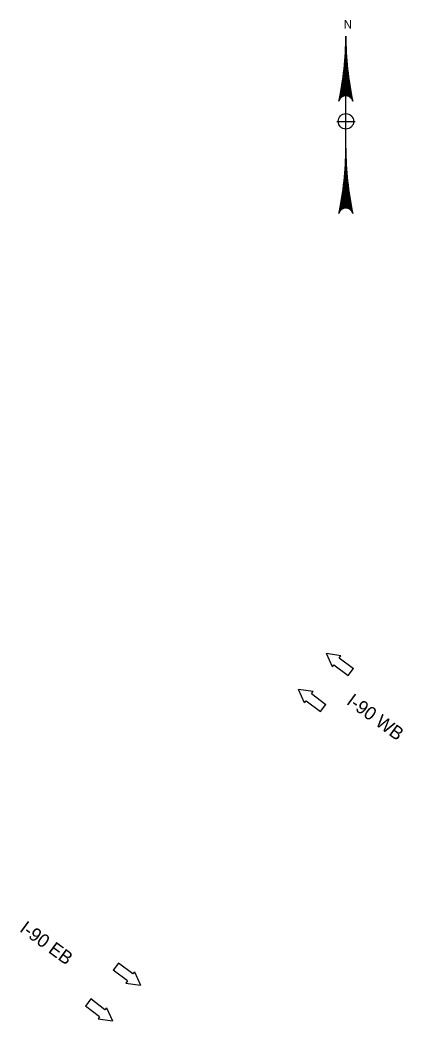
# Model space of a CAD drawing. Extents: x 337137 to 337603, y 1540940 to 1541587.
# Drawn here: x 337136.6 to 337226.9, y 1541351.2 to 1541586.5 of the extents above; entities that cross this region are included whole.
import ezdxf

# ---------------------------------------------------------------- set-up
doc = ezdxf.new("R2010")
doc.units = 0
for name, color, linetype in [('O_Details_Dimensions_Notes_P', 7, 'Continuous'), ('O_Details_Object Line 1_P', 7, 'Continuous'), ('O_Details_Text Normal Proposed_P_T', 7, 'Continuous')]:
    doc.layers.add(name, color=color, linetype=linetype)

msp = doc.modelspace()

# ---------------------------------------------------------------- linework, layer by layer
at = {"layer": 'O_Details_Object Line 1_P'}
for p, q in [((337212.06, 1541437.04), (337208.67, 1541437.53)), ((337210.07, 1541434.41), (337208.67, 1541437.53)), ((337211.69, 1541436.56), (337212.06, 1541437.04)), ((337211.69, 1541436.56), (337215.05, 1541434.04)), ((337210.07, 1541434.41), (337210.43, 1541434.89)), ((337210.43, 1541434.89), (337213.79, 1541432.36)), ((337213.79, 1541432.36), (337215.05, 1541434.04)), ((337205.51, 1541428.61), (337202.13, 1541429.1)), ((337203.53, 1541425.97), (337202.13, 1541429.1)), ((337205.15, 1541428.13), (337205.51, 1541428.61)), ((337205.15, 1541428.13), (337208.51, 1541425.6)), ((337203.53, 1541425.97), (337203.89, 1541426.45)), ((337203.89, 1541426.45), (337207.25, 1541423.93)), ((337207.25, 1541423.93), (337208.51, 1541425.6)), ((337159.79, 1541364.77), (337158.53, 1541363.09)), ((337161.89, 1541360.57), (337158.53, 1541363.09)), ((337163.15, 1541362.24), (337159.79, 1541364.77)), ((337163.51, 1541362.72), (337163.15, 1541362.24)), ((337163.51, 1541362.72), (337164.92, 1541359.6)), ((337161.89, 1541360.57), (337161.53, 1541360.09)), ((337161.53, 1541360.09), (337164.92, 1541359.6)), ((337153.25, 1541356.34), (337151.99, 1541354.66)), ((337156.61, 1541353.81), (337153.25, 1541356.34)), ((337155.35, 1541352.13), (337151.99, 1541354.66)), ((337156.97, 1541354.29), (337156.61, 1541353.81)), ((337156.97, 1541354.29), (337158.37, 1541351.17)), ((337155.35, 1541352.13), (337154.99, 1541351.65)), ((337154.99, 1541351.65), (337158.37, 1541351.17))]:
    msp.add_line(p, q, dxfattribs=at)
at = {"layer": 'O_Details_Text Normal Proposed_P_T'}
for p, q in [((337213.23, 1541542.27), (337213.23, 1541582.73)), ((337213.23, 1541542.27), (337213.23, 1541582.73)), ((337213.23, 1541542.27), (337213.23, 1541582.73)), ((337213.23, 1541542.27), (337213.23, 1541582.73)), ((337213.03, 1541568.63), (337213.03, 1541577.23)), ((337213.12, 1541568.65), (337213.12, 1541578.79)), ((337213.33, 1541568.65), (337213.33, 1541578.79)), ((337213.43, 1541568.63), (337213.43, 1541577.23)), ((337212.86, 1541568.6), (337212.86, 1541575.24)), ((337212.95, 1541568.63), (337212.95, 1541576.05)), ((337213.52, 1541568.63), (337213.52, 1541576.05)), ((337213.61, 1541568.6), (337213.61, 1541575.24)), ((337212.59, 1541568.5), (337212.59, 1541573.03)), ((337212.68, 1541568.56), (337212.68, 1541573.68)), ((337212.77, 1541568.58), (337212.77, 1541574.44)), ((337213.7, 1541568.58), (337213.7, 1541574.44)), ((337213.79, 1541568.56), (337213.79, 1541573.68)), ((337213.88, 1541568.5), (337213.88, 1541573.03)), ((337212.22, 1541568.31), (337212.22, 1541570.59)), ((337212.31, 1541568.37), (337212.31, 1541571.14)), ((337212.4, 1541568.42), (337212.4, 1541571.67)), ((337212.49, 1541568.48), (337212.49, 1541572.39)), ((337213.98, 1541568.48), (337213.98, 1541572.39)), ((337214.06, 1541568.42), (337214.06, 1541571.67)), ((337214.15, 1541568.37), (337214.15, 1541571.14)), ((337214.24, 1541568.31), (337214.24, 1541570.59)), ((337211.76, 1541567.78), (337211.76, 1541568.18)), ((337211.85, 1541567.94), (337211.85, 1541568.63)), ((337211.94, 1541568.06), (337211.94, 1541569.08)), ((337212.03, 1541568.15), (337212.03, 1541569.59)), ((337212.13, 1541568.24), (337212.13, 1541570.08)), ((337214.33, 1541568.24), (337214.33, 1541570.08)), ((337214.42, 1541568.15), (337214.42, 1541569.59)), ((337214.51, 1541568.06), (337214.51, 1541569.08)), ((337214.61, 1541567.94), (337214.61, 1541568.63)), ((337214.7, 1541567.78), (337214.7, 1541568.18)), ((337211.09, 1541562.68), (337215.41, 1541562.68)), ((337213.12, 1541542.27), (337213.12, 1541552.41)), ((337213.33, 1541542.27), (337213.33, 1541552.41)), ((337212.94, 1541542.25), (337212.94, 1541549.68)), ((337213.03, 1541542.27), (337213.03, 1541550.86)), ((337213.43, 1541542.27), (337213.43, 1541550.86)), ((337213.52, 1541542.25), (337213.52, 1541549.68)), ((337212.59, 1541542.13), (337212.59, 1541546.65)), ((337212.68, 1541542.17), (337212.68, 1541547.29)), ((337212.77, 1541542.21), (337212.77, 1541548.07)), ((337212.85, 1541542.23), (337212.85, 1541548.87)), ((337213.61, 1541542.23), (337213.61, 1541548.87)), ((337213.7, 1541542.21), (337213.7, 1541548.07)), ((337213.79, 1541542.17), (337213.79, 1541547.29)), ((337213.87, 1541542.13), (337213.87, 1541546.65)), ((337212.31, 1541542), (337212.31, 1541544.76)), ((337212.4, 1541542.06), (337212.4, 1541545.3)), ((337212.49, 1541542.09), (337212.49, 1541546.02)), ((337213.96, 1541542.09), (337213.96, 1541546.02)), ((337214.06, 1541542.06), (337214.06, 1541545.3)), ((337214.15, 1541542), (337214.15, 1541544.76)), ((337211.85, 1541541.57), (337211.85, 1541542.25)), ((337211.94, 1541541.67), (337211.94, 1541542.71)), ((337212.03, 1541541.77), (337212.03, 1541543.21)), ((337212.13, 1541541.86), (337212.13, 1541543.71)), ((337212.22, 1541541.94), (337212.22, 1541544.21)), ((337214.24, 1541541.94), (337214.24, 1541544.21)), ((337214.33, 1541541.86), (337214.33, 1541543.71)), ((337214.42, 1541541.77), (337214.42, 1541543.21)), ((337214.51, 1541541.67), (337214.51, 1541542.71)), ((337214.61, 1541541.57), (337214.61, 1541542.25)), ((337211.76, 1541541.41), (337211.76, 1541541.81)), ((337214.7, 1541541.41), (337214.7, 1541541.81))]:
    msp.add_line(p, q, dxfattribs=at)
for centre, major_axis, start_param, end_param in [((337140.39, 1541582.72), (0, 72.85), 4.500924, 4.712548), ((337286.07, 1541582.72), (0, -72.85), 4.71223, 4.923854), ((337213.25, 1541567), (0, 1.69), 4.940004, 7.602623), ((337140.39, 1541556.34), (0, 72.85), 4.500924, 4.712548), ((337286.07, 1541556.34), (0, -72.85), 4.71223, 4.923854), ((337213.23, 1541540.59), (0, 1.69), 4.989805, 7.57658)]:
    msp.add_ellipse(centre, major_axis=major_axis, ratio=0.999821, start_param=start_param, end_param=end_param, dxfattribs=at)
msp.add_ellipse((337213.25, 1541562.68), major_axis=(0, -1.81), ratio=0.999821, dxfattribs=at)

# ---------------------------------------------------------------- texts
at = {"layer": 'O_Details_Dimensions_Notes_P'}
for s, p in [('I-90 WB', (337213.18, 1541425.83)), ('I-90 EB', (337136.33, 1541372.38))]:
    msp.add_text(s, height=3.125, rotation=323.8105, dxfattribs=at).set_placement(p)
at = {"layer": 'O_Details_Text Normal Proposed_P_T'}
msp.add_text('N', height=2, rotation=360, dxfattribs=at).set_placement((337212.74, 1541584.5))

doc.saveas('drawing.dxf')
